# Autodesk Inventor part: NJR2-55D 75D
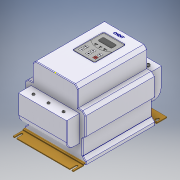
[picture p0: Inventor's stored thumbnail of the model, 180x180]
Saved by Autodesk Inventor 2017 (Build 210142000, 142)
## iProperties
Part Number: NJR2-55D 75D
Material: Типовые
Document SubType Name: Modeling
Designer: RSagdiev
Density: 1 g/cm^3
Appearance: По умолчанию
Author: RSagdiev
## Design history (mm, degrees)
sketch "Эскиз1"
  geometry: L1 (0, 0)-(14.471, 0) reference; L2 (0, 0)-(0, 21.118) reference; L3 (0, 0)-(230, 0); L4 (230, 0)-(230, 20); L5 (230, 215)-(0, 215); L6 (0, 215)-(0, 150); L7 (230, 20)-(0, 20); L8 (230, 70)-(0, 70); L9 (230, 70)-(230, 150); L10 (230, 20)-(230, 70); L11 (0, 70)-(0, 20); L12 (0, 20)-(0, 0); L13 (230, 150)-(0, 150); L14 (230, 150)-(230, 215); L15 (0, 150)-(0, 70)
  constraints: 30 end point, 17 parallel, 14 perpendicular, 3 horizontal, 2 vertical, 1 point on line
  dimensions: "d0" = 230 distance of L5.end L5.start; "d1" = 215 distance of L5.start L3.end; "d2" = 20 distance between parallel lines of L3 L7; "d3" = 50 distance between parallel lines of L8 L7; "d4" = 80 distance between parallel lines of L13 L8
extrude "Выдавливание1" new body sketch "Эскиз1" stored distance "d5" = 202; taper "d6" = 0 deg
extrude "Выдавливание2" join sketch "Эскиз1" stored distance "d7" = 180; taper "d8" = 0 deg
extrude "Выдавливание3" join sketch "Эскиз1" stored distance "d9" = 200; taper "d10" = 0 deg
extrude "Выдавливание4" join sketch "Эскиз1" stored distance "d11" = 150; taper "d12" = 0 deg
chamfer "Фаска1" distance "d13" = 10; stored, may be unused: second distance "d14" = 2, angle "d15" = 45 deg
sketch "Эскиз2"
  geometry: L1 (270, 0)-(236, 0); L2 (235, 1)-(235, 3); L3 (234, 4)-(-4, 4); L4 (-5, 3)-(-5, 1); L5 (-6, 0)-(-40, 0); L6 (230, 10)-(230, 0) reference; L7 (230, 0)-(0, 0) reference; L8 (0, 0)-(0, 10) reference; L9 (270, 3)-(238, 3); L10 (234, 7)-(-4, 7); L11 (-8, 3)-(-40, 3); L12 (-40, 0)-(-40, 3); L13 (270, 3)-(270, 0); A1 r 1 centre (-6, 1) between (-6, 0) and (-5, 1); A2 r 1 centre (-4, 3) between (-4, 4) and (-5, 3); A3 r 1 centre (236, 1) between (235, 1) and (236, 0); A4 r 1 centre (234, 3) between (235, 3) and (234, 4); A5 r 4 centre (234, 3) between (238, 3) and (234, 7); A6 r 4 centre (-4, 3) between (-4, 7) and (-8, 3); 4 further points
  constraints: 20 end point, 12 point on circle, 10 point on line, 8 tangent, 6 centre point, 4 perpendicular, 3 equal radius, 1 horizontal, 1 parallel, 4 other
  dimensions: "d16" = 4 distance of point (235, 0) point (235, 4); "d17" = 5 distance between parallel lines of L2 L6; "d18" = 4 distance between parallel lines of L7 L3; "d19" = 35 distance of point (235, 0) L1.start; "d20" = 35 distance of point (-5, 0) L5.end (= d19); "d21" = 4 distance of point (-5, 4) point (-5, 0) (derived); "d22" = 5 distance between parallel lines of L4 L8 (= d17); "d23" = 310 distance of L5.end L1.start (derived); "d24" = 1 radius of A1; "d25" = 3 distance between parallel lines of L1 L9
extrude "Выдавливание5" new body sketch "Эскиз2" stored distance "d26" = 200; taper "d27" = 0 deg
sketch "Эскиз4"
  geometry: L1 (272.5, 138)-(-42.5, 138); L2 (-42.5, 138)-(-42.5, 50); L3 (-42.5, 50)-(272.5, 50); L4 (272.5, 50)-(272.5, 138); L5 (230, 150)-(230, 205) reference; L6 (230, 150)-(0, 150) reference; L7 (230, 70)-(0, 70) reference; 1 further point
  constraints: 8 end point, 2 parallel, 1 horizontal, 1 perpendicular
  dimensions: "d28" = 315 distance between parallel lines of L2 L4; "d29" = 42.5 distance between parallel lines of L4 L5 (= -0.5 x d0 + 0.5 x d28); "d31" = 20 distance between parallel lines of L7 L3; "d34" = 12 distance between parallel lines of L1 L6
extrude "Выдавливание6" join sketch "Эскиз4" stored distance "d32" = 160; taper "d33" = 0 deg
fillet "Сопряжение1" dims "d35" = 25
sketch "Эскиз5" dims "d44" = 10
  geometry: L1 (160, 0)-(0, 0) reference; L2 (160, 42.5)-(160, 0) reference; L3 (160, 42.5)-(0, 42.5) reference; L4 (0, 0)-(0, 42.5) reference; C1 r 4 at (20, 20); C2 r 4 at (43.333, 20); C3 r 4 at (66.667, 20); C4 r 4 at (90, 20); C5 r 4 at (113.333, 20); C6 r 4 at (136.667, 20); 1 further point
  constraints: 6 centre point, 1 horizontal, 10 other
  dimensions: "d36" = 8 diameter of C1; "d37" = 160 distance between parallel lines of L2 L4 (derived); "d38" = 20 distance from line of C1.centre L4; "d41" = 23.33333 distance of C1.centre C2.centre (= -0.166667 x d38 + 0.166667 x d37)
  node "Спроецированная петля1"
extrude "Выдавливание7" cut sketch "Эскиз5" distance "d46" = 20; taper "d47" = 0 deg
extrude "Выдавливание8" new body sketch "Эскиз5" distance "d48" = 20; taper "d49" = 0 deg
sketch "Эскиз6" dims "d50" = 12, "d56" = 10
  geometry: L1 (0, 6)-(5.196, 3); L2 (5.196, 3)-(5.196, -3); L3 (5.196, -3)-(0, -6); L4 (0, -6)-(-5.196, -3); L5 (-5.196, -3)-(-5.196, 3); L6 (-5.196, 3)-(0, 6); L7 (140, 22.5)-(-20, 22.5) reference; L8 (23.333, 6)-(28.529, 3); L9 (28.529, 3)-(28.529, -3); L10 (28.529, -3)-(23.333, -6); L11 (23.333, -6)-(18.137, -3); L12 (18.137, -3)-(18.137, 3); L13 (18.137, 3)-(23.333, 6); L14 (46.667, 6)-(51.863, 3); L15 (51.863, 3)-(51.863, -3); L16 (51.863, -3)-(46.667, -6); L17 (46.667, -6)-(41.471, -3); L18 (41.471, -3)-(41.471, 3); L19 (41.471, 3)-(46.667, 6); L20 (70, 6)-(75.196, 3); L21 (75.196, 3)-(75.196, -3); L22 (75.196, -3)-(70, -6); L23 (70, -6)-(64.804, -3); L24 (64.804, -3)-(64.804, 3); L25 (64.804, 3)-(70, 6); L26 (93.333, 6)-(98.529, 3); L27 (98.529, 3)-(98.529, -3); L28 (98.529, -3)-(93.333, -6); L29 (93.333, -6)-(88.137, -3); L30 (88.137, -3)-(88.137, 3); L31 (88.137, 3)-(93.333, 6); L32 (116.667, 6)-(121.863, 3); L33 (121.863, 3)-(121.863, -3); L34 (121.863, -3)-(116.667, -6); L35 (116.667, -6)-(111.471, -3); L36 (111.471, -3)-(111.471, 3); L37 (111.471, 3)-(116.667, 6); 13 further points
  constraints: 72 end point, 6 coincident, 6 horizontal, 6 vertical alignment, 95 other
  dimensions: "d53" = 23.33333 distance of point (0, 0) point (23.333, 0) (= -0.166667 x d38 + 0.166667 x d37)
extrude "Выдавливание9" join sketch "Эскиз6" distance "d58" = 5; taper "d59" = 0 deg
sketch "Эскиз7"
  geometry: L1 (5.196, 3)-(0, 6) reference; L2 (0, 6)-(-5.196, 3) reference; L3 (-5.196, 3)-(-5.196, -3) reference; L4 (-5.196, -3)-(0, -6) reference; L5 (0, -6)-(5.196, -3) reference; L6 (5.196, -3)-(5.196, 3) reference; L7 (0, 3.691)-(3.196, 1.845); L8 (3.196, 1.845)-(3.196, -1.845); L9 (3.196, -1.845)-(0, -3.691); L10 (0, -3.691)-(-3.196, -1.845); L11 (-3.196, -1.845)-(-3.196, 1.845); L12 (-3.196, 1.845)-(0, 3.691); L13 (28.529, 3)-(23.333, 6) reference; L14 (23.333, 6)-(18.137, 3) reference; L15 (18.137, 3)-(18.137, -3) reference; L16 (18.137, -3)-(23.333, -6) reference; L17 (23.333, -6)-(28.529, -3) reference; L18 (28.529, -3)-(28.529, 3) reference; L19 (51.863, 3)-(46.667, 6) reference; L20 (46.667, 6)-(41.471, 3) reference; L21 (41.471, 3)-(41.471, -3) reference; L22 (41.471, -3)-(46.667, -6) reference; L23 (46.667, -6)-(51.863, -3) reference; L24 (51.863, -3)-(51.863, 3) reference; L25 (75.196, 3)-(70, 6) reference; L26 (70, 6)-(64.804, 3) reference; L27 (64.804, 3)-(64.804, -3) reference; L28 (64.804, -3)-(70, -6) reference; L29 (70, -6)-(75.196, -3) reference; L30 (75.196, -3)-(75.196, 3) reference; L31 (98.529, 3)-(93.333, 6) reference; L32 (93.333, 6)-(88.137, 3) reference; L33 (88.137, 3)-(88.137, -3) reference; L34 (88.137, -3)-(93.333, -6) reference; L35 (93.333, -6)-(98.529, -3) reference; L36 (98.529, -3)-(98.529, 3) reference; L37 (121.863, 3)-(116.667, 6) reference; L38 (116.667, 6)-(111.471, 3) reference; L39 (111.471, 3)-(111.471, -3) reference; L40 (111.471, -3)-(116.667, -6) reference; L41 (116.667, -6)-(121.863, -3) reference; L42 (121.863, -3)-(121.863, 3) reference; L43 (23.333, 3.691)-(26.529, 1.845); L44 (26.529, 1.845)-(26.529, -1.845); L45 (26.529, -1.845)-(23.333, -3.691); L46 (23.333, -3.691)-(20.137, -1.845); L47 (20.137, -1.845)-(20.137, 1.845); L48 (20.137, 1.845)-(23.333, 3.691); L49 (43.471, 1.845)-(46.667, 3.691); L50 (46.667, 3.691)-(49.863, 1.845); L51 (49.863, 1.845)-(49.863, -1.845); L52 (49.863, -1.845)-(46.667, -3.691); L53 (46.667, -3.691)-(43.471, -1.845); L54 (43.471, -1.845)-(43.471, 1.845); L55 (66.804, 1.845)-(70, 3.691); L56 (70, 3.691)-(73.196, 1.845); L57 (73.196, 1.845)-(73.196, -1.845); L58 (73.196, -1.845)-(70, -3.691); L59 (70, -3.691)-(66.804, -1.845); L60 (66.804, -1.845)-(66.804, 1.845); L61 (90.137, 1.845)-(93.333, 3.691); L62 (93.333, 3.691)-(96.529, 1.845); L63 (96.529, 1.845)-(96.529, -1.845); L64 (96.529, -1.845)-(93.333, -3.691)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; 1 further point
  constraints: 72 end point, 30 other
  dimensions: "d60" = 2 distance between parallel lines of L1 L7; "d61" = 2 distance between parallel lines of L13 L43; "d62" = 2 distance between parallel lines of L20 L49; "d63" = 2 distance between parallel lines of L26 L55; "d64" = 2 distance between parallel lines of L32 L61; "d65" = 2 distance between parallel lines of L38 L67
extrude "Выдавливание10" cut sketch "Эскиз7" distance "d66" = 1.5; taper "d67" = 0 deg
fillet "Сопряжение2" dims "d68" = 2
sketch "Эскиз8"
  geometry: L1 (0, -310)-(200, -310) reference; L2 (200, 0)-(0, 0) reference; L3 (200, 0)-(200, -34) reference; L4 (0, -34)-(0, 0) reference; L5 (8.5, -20)-(8.5, -25); L6 (191.5, -20)-(191.5, -25); L7 (8.5, -20)-(191.5, -20); L8 (8.5, -290)-(8.5, -310); L9 (5, -290)-(5, -310); L10 (12, -310)-(12, -290); L11 (8.5, -20)-(8.5, -290); L12 (8.5, -290)-(191.5, -290); L13 (191.5, -20)-(191.5, -290); L14 (191.5, -290)-(191.5, -310); L15 (188, -290)-(188, -310); L16 (195, -310)-(195, -290); A1 r 3.5 centre (8.5, -20) between (11.779, -21.225) and (5.221, -21.225); A2 r 5 centre (8.5, -25) between (5.221, -21.225) and (11.779, -21.225); A3 r 3.5 centre (191.5, -20) between (194.779, -21.225) and (188.221, -21.225); A4 r 5 centre (191.5, -25) between (188.221, -21.225) and (194.779, -21.225); A5 r 3.5 centre (8.5, -290) between (12, -290) and (5, -290); A6 r 3.5 centre (8.5, -310) between (5, -310) and (12, -310); A7 r 3.5 centre (191.5, -290) between (195, -290) and (188, -290); A8 r 3.5 centre (191.5, -310) between (188, -310) and (195, -310); 5 further points
  constraints: 28 end point, 16 point on circle, 8 centre point, 8 tangent, 4 vertical, 3 coincident, 2 horizontal, 2 midpoint, 2 parallel, 2 perpendicular, 2 point on line
  dimensions: "d69" = 183 distance of point (191.5, -20) point (8.5, -20); "d70" = 270 distance of L8.start point (8.5, -20); "d71" = 310 distance between parallel lines of L1 L2 (derived); "d72" = 20 distance from line of L2 point (8.5, -20) (= -0.5 x d70 + 0.5 x d71); "d73" = 200 distance between parallel lines of L3 L4 (derived); "d74" = 8.5 distance from line of L4 point (8.5, -20) (= -0.5 x d69 + 0.5 x d73); "d75" = 7 diameter of A1; "d76" = 10 diameter of A2; "d77" = 5 distance of L5.start L5.end; "d78" = 7 diameter of A3; "d79" = 10 diameter of A4; "d80" = 5 distance of L6.start L6.end; "d81" = 7 diameter of A6; "d82" = 7 diameter of A8
extrude "Выдавливание11" cut sketch "Эскиз8" distance "d83" = 5.5; taper "d84" = 0 deg
fillet "Сопряжение3" dims "d85" = 2
sketch "Эскиз9"
  geometry: L1 (130, 0)-(0, 0) reference; L2 (130, 226)-(130, 0) reference; L3 (0, 226)-(130, 226) reference; L4 (0, 0)-(0, 226) reference; L5 (33, 193)-(97, 193); L6 (100, 190)-(100, 96); L7 (97, 93)-(33, 93); L8 (30, 96)-(30, 190); L9 (97, 195)-(33, 195); L10 (28, 190)-(28, 96); L11 (33, 91)-(97, 91); L12 (102, 96)-(102, 190); A1 r 3 centre (33, 190) between (33, 193) and (30, 190); A2 r 3 centre (97, 190) between (100, 190) and (97, 193); A3 r 3 centre (97, 96) between (97, 93) and (100, 96); A4 r 3 centre (33, 96) between (30, 96) and (33, 93); A5 r 5 centre (33, 190) between (33, 195) and (28, 190); A6 r 5 centre (33, 96) between (28, 96) and (33, 91); A7 r 5 centre (97, 96) between (97, 91) and (102, 96); A8 r 5 centre (97, 190) between (102, 190) and (97, 195); 4 further points
  constraints: 16 end point, 16 point on circle, 8 centre point, 8 tangent, 6 point on line, 4 parallel, 3 equal radius, 2 perpendicular, 1 horizontal, 7 other
  dimensions: "d86" = 70 distance of point (100, 93) point (30, 93); "d87" = 100 distance of point (100, 193) point (100, 93); "d88" = 130 distance of L3.start L2.start (derived); "d89" = 226 distance of L1.end L3.start (derived); "d90" = 33 distance between parallel lines of L3 L5 (computed from d89, d87); "d91" = 30 distance between parallel lines of L4 L8 (= -0.5 x d86 + 0.5 x d88); "d92" = 3 radius of A1; "d93" = 2 distance between parallel lines of L5 L9
  node "Спроецированная петля8"
extrude "Выдавливание12" cut sketch "Эскиз9" distance "d94" = 25; taper "d95" = 0 deg
extrude "Выдавливание13" new body sketch "Эскиз9" distance "d96" = 25; taper "d97" = 0 deg
sketch "Эскиз10"
  geometry: L1 (30, 190)-(30, 150.574); L2 (33, 93)-(97, 93); L3 (100, 96)-(100, 150.574); L4 (97, 193)-(33, 193); L5 (97, 193)-(33, 193) reference; L6 (30, 190)-(30, 96) reference; L7 (30, 150.574)-(30, 96); L8 (100, 150.574)-(100, 190); L9 (45.628, 161.287)-(84.628, 161.287); L10 (87.628, 164.287)-(87.628, 176.287); L11 (84.628, 179.287)-(45.628, 179.287); L12 (42.628, 176.287)-(42.628, 164.287); L13 (42.628, 161.287)-(87.628, 179.287); L14 (87.628, 161.287)-(42.628, 179.287); A1 r 3 centre (33, 96) between (30, 96) and (33, 93); A2 r 3 centre (97, 96) between (97, 93) and (100, 96); A3 r 3 centre (97, 190) between (100, 190) and (97, 193); A4 r 3 centre (33, 190) between (33, 193) and (30, 190); A5 r 55 centre (65, 193) between (30, 150.574) and (100.197, 150.737); A6 r 3 centre (45.628, 176.287) between (45.628, 179.287) and (42.628, 176.287); A7 r 3 centre (45.628, 164.287) between (42.628, 164.287) and (45.628, 161.287); A8 r 3 centre (84.628, 176.287) between (87.628, 176.287) and (84.628, 179.287); A9 r 3 centre (84.628, 164.287) between (84.628, 161.287) and (87.628, 164.287); 2 further points
  constraints: 20 end point, 11 point on circle, 9 centre point, 9 point on line, 8 tangent, 3 equal radius, 3 midpoint, 2 parallel, 1 horizontal, 1 perpendicular
  dimensions: "d98" = 55 radius of A5; "d99" = 45 distance of L14.end L13.end; "d100" = 18 distance of L13.end L14.start; "d101" = 22.7132 distance from line of L4 point (65.128, 170.287); "d102" = 35.1281 distance from line of L1 point (65.128, 170.287); "d103" = 3 radius of A6 (derived)
extrude "Выдавливание14" cut sketch "Эскиз10" distance "d104" = 1; taper "d105" = 0 deg
sketch "Эскиз11"
  geometry: L1 (30, 150.574)-(30, 96) reference; L2 (33, 93)-(97, 93) reference; L3 (100, 96)-(100, 150.574) reference; L4 (30, 150.574)-(30, 96) reference; L5 (30, 123)-(100, 123); L6 (100, 96)-(100, 150.574) reference; L7 (30, 108)-(100, 108); L8 (33, 93)-(97, 93) reference; L9 (41.667, 93)-(41.667, 143.195); L10 (88.333, 93)-(88.333, 143.195); L11 (65, 93)-(65, 138); L12 (36.667, 128)-(46.667, 128); L13 (46.667, 128)-(46.667, 118); L14 (46.667, 118)-(36.667, 118); L15 (36.667, 118)-(36.667, 128); L16 (36.667, 128)-(46.667, 118); L17 (46.667, 128)-(36.667, 118); L18 (36.667, 113)-(46.667, 113); L19 (46.667, 113)-(46.667, 103); L20 (46.667, 103)-(36.667, 103); L21 (36.667, 103)-(36.667, 113); L22 (36.667, 113)-(46.667, 103); L23 (46.667, 113)-(36.667, 103); L24 (60, 128)-(70, 128); L25 (70, 128)-(70, 118); L26 (70, 118)-(60, 118); L27 (60, 118)-(60, 128); L28 (60, 128)-(70, 118); L29 (70, 128)-(60, 118); L30 (60, 113)-(70, 113); L31 (70, 113)-(70, 103); L32 (70, 103)-(60, 103); L33 (60, 103)-(60, 113); L34 (60, 113)-(70, 103); L35 (70, 113)-(60, 103); L36 (83.333, 128)-(93.333, 128); L37 (93.333, 128)-(93.333, 118); L38 (93.333, 118)-(83.333, 118); L39 (83.333, 118)-(83.333, 128); L40 (83.333, 128)-(93.333, 118); L41 (93.333, 128)-(83.333, 118); L42 (83.333, 113)-(93.333, 113); L43 (93.333, 113)-(93.333, 103); L44 (93.333, 103)-(83.333, 103); L45 (83.333, 103)-(83.333, 113); L46 (83.333, 113)-(93.333, 103); L47 (93.333, 113)-(83.333, 103); L48 (46.767, 128.1)-(36.567, 128.1); L49 (36.567, 128.1)-(36.567, 117.9); L50 (36.567, 117.9)-(46.767, 117.9); L51 (46.767, 117.9)-(46.767, 128.1); L52 (70.1, 128.1)-(59.9, 128.1); L53 (59.9, 128.1)-(59.9, 117.9); L54 (59.9, 117.9)-(70.1, 117.9); L55 (70.1, 117.9)-(70.1, 128.1); L56 (93.433, 128.1)-(83.233, 128.1); L57 (83.233, 128.1)-(83.233, 117.9); L58 (83.233, 117.9)-(93.433, 117.9); L59 (93.433, 117.9)-(93.433, 128.1); L60 (46.767, 113.1)-(36.567, 113.1); L61 (36.567, 113.1)-(36.567, 102.9); L62 (36.567, 102.9)-(46.767, 102.9); L63 (46.767, 102.9)-(46.767, 113.1); L64 (70.1, 113.1)-(59.9, 113.1)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; A1 r 55 centre (65, 193) between (30, 150.574) and (100, 150.574) reference; A2 r 3 centre (33, 96) between (30, 96) and (33, 93) reference; A3 r 3 centre (97, 96) between (97, 93) and (100, 96) reference; A4 r 55 centre (65, 193) between (30, 150.574) and (100, 150.574) reference; 8 further points
  constraints: 130 end point, 24 parallel, 16 midpoint, 16 point on line, 14 perpendicular, 7 horizontal, 4 point on circle, 1 vertical, 18 other
  dimensions: "d106" = 70 distance between parallel lines of L3 L1 (derived); "d107" = 45 distance from line of L2 L11.end (derived); "d108" = 15 distance between parallel lines of L7 L5 (= 0.333333 x d107); "d109" = 15 distance from line of L11.end L5 (= 0.333333 x d107); "d110" = 23.33333 distance between parallel lines of L11 L10 (= 0.333333 x d106); "d111" = 23.33333 distance between parallel lines of L11 L9 (= d110); "d112" = 10 distance of L13.end L14.end; "d113" = 10 distance of L12.end L13.end; "d114" = 10 distance of L19.end L20.end; "d115" = 10 distance of L18.end L19.end; "d116" = 10 distance of L25.end L26.end; "d117" = 10 distance of L24.end L25.end; "d118" = 10 distance of L31.end L32.end; "d119" = 10 distance of L30.end L31.end; "d120" = 10 distance of L37.end L38.end; "d121" = 10 distance of L36.end L37.end; "d122" = 10 distance of L43.end L44.end; "d123" = 10 distance of L42.end L43.end; "d124" = 0.1 distance between parallel lines of L12 L48; "d125" = 0.1 distance between parallel lines of L24 L52; "d126" = 0.1 distance between parallel lines of L36 L56; "d127" = 0.1 distance between parallel lines of L18 L60; "d128" = 0.1 distance between parallel lines of L30 L64; "d129" = 0.1 distance between parallel lines of L42 L68
extrude "Выдавливание15" cut sketch "Эскиз11" distance "d130" = 3; taper "d131" = 0 deg
sketch "Эскиз12"
  geometry: L1 (100, 96)-(100, 150.574) reference; L2 (50, 144.701)-(80, 144.701); C1 r 1.5 at (65, 144.701); C2 r 1.5 at (80, 144.701); C3 r 1.5 at (50, 144.701); C4 r 1.6 at (50, 144.701); C5 r 1.6 at (65, 144.701); C6 r 1.6 at (80, 144.701); A1 r 55 centre (65, 193) between (30, 150.574) and (100, 150.574) reference; 1 further point
  constraints: 6 centre point, 2 end point, 1 coincident, 1 horizontal, 1 midpoint
  dimensions: "d132" = 3 diameter of C1; "d133" = 3 diameter of C2; "d134" = 3 diameter of C3; "d135" = 48.29941 distance of A1.centre C1.centre; "d136" = 35 distance from line of L1 C1.centre; "d137" = 15 distance of C1.centre C2.centre; "d138" = 15 distance of C1.centre L2.start; "d139" = 0.1 radial gap between concentric circles of C3 C4; "d140" = 0.1 radial gap between concentric circles of C1 C5; "d141" = 0.1 radial gap between concentric circles of C2 C6
extrude "Выдавливание16" cut sketch "Эскиз12" distance "d142" = 3; taper "d143" = 0 deg
sketch "Эскиз13"
  geometry: L1 (45, 150.348)-(102.075, 150.348); L2 (102.075, 150.348)-(102.075, 146.701); L3 (102.075, 146.701)-(45, 146.701); L4 (45, 146.701)-(45, 150.348); C1 r 1.5 at (50, 144.701) reference; 1 further point
  constraints: 2 other
  dimensions: "d144" = 2 vertical distance of L3.end C1.centre; "d145" = 5 horizontal distance of C1.centre L3.end
feature "Рельеф1" sketch "Эскиз13" dims "d146" = 0.1, "d147" = 0
sketch "Эскиз14"
  geometry: L1 (36.734, 124.406)-(51.145, 124.406); L2 (51.145, 124.406)-(51.145, 120.906); L3 (51.145, 120.906)-(36.734, 120.906); L4 (36.734, 120.906)-(36.734, 124.406); L5 (38.873, 106.059)-(38.873, 109.559); L6 (38.873, 109.559)-(53.285, 109.559); L7 (53.285, 109.559)-(53.285, 106.059); L8 (53.285, 106.059)-(38.873, 106.059); L9 (84.699, 105.985)-(84.699, 109.485); L10 (84.699, 109.485)-(99.11, 109.485); L11 (99.11, 109.485)-(99.11, 105.985); L12 (99.11, 105.985)-(84.699, 105.985); L13 (85.21, 120.906)-(85.21, 124.406); L14 (85.21, 124.406)-(99.621, 124.406); L15 (99.621, 124.406)-(99.621, 120.906); L16 (99.621, 120.906)-(85.21, 120.906); 1 further point
  constraints: 8 other
feature "Рельеф2" dims "d148" = 0.1, "d149" = 0
feature "Рельеф3" dims "d150" = 0.1, "d151" = 0
feature "Рельеф4" dims "d152" = 0.1, "d153" = 0
feature "Рельеф5" dims "d154" = 0.1, "d155" = 0
sketch "Эскиз15" dims "d156" = 6, "d157" = 6
  geometry: L1 (60, 128)-(60, 118) reference; L2 (60, 118)-(70, 118) reference; L3 (70, 118)-(70, 128) reference; L4 (70, 128)-(60, 128) reference; L5 (60, 113)-(60, 103) reference; L6 (60, 103)-(70, 103) reference; L7 (70, 103)-(70, 113) reference; L8 (70, 113)-(60, 113) reference; L9 (60, 118)-(70, 128); L10 (60, 128)-(70, 118); L11 (60, 113)-(70, 103); L12 (70.1, 113.1)-(70.1, 102.9) reference; L13 (70.1, 113.1)-(60, 103); L14 (65.05, 126)-(67.573, 121.457); L15 (67.573, 121.457)-(62.377, 121.544); L16 (62.377, 121.544)-(65.05, 126); L17 (65.05, 105.05)-(62.452, 109.55); L18 (62.452, 109.55)-(67.648, 109.55); L19 (67.648, 109.55)-(65.05, 105.05); 5 further points
  constraints: 20 end point, 2 coincident, 2 midpoint, 2 perpendicular, 1 parallel, 1 vertical alignment, 19 other
  node "Спроецированная петля11"
  node "Спроецированная петля12"
feature "Рельеф6" dims "d158" = 0.1, "d159" = 0
feature "Рельеф7" dims "d160" = 0.1, "d161" = 0
sketch "Эскиз16"
  geometry: L1 (2, -42.5)-(158, -42.5) reference; L2 (160, 0)-(160, -40.5) reference; L3 (0, 0)-(160, 0) reference; L4 (0, -40.5)-(0, 0) reference; L5 (130, -22.5)-(0, -22.5); L6 (0, -40.5)-(0, -17.5) reference; C1 r 4 at (30, -22.5); C2 r 4 at (80, -22.5); C3 r 4 at (130, -22.5); A1 r 2 centre (2, -40.5) between (0, -40.5) and (2, -42.5) reference; A2 r 2 centre (158, -40.5) between (158, -42.5) and (160, -40.5) reference; 1 further point
  constraints: 3 centre point, 3 point on line, 2 end point, 1 horizontal
  dimensions: "d162" = 8 diameter of C1; "d163" = 8 diameter of C2; "d164" = 8 diameter of C3; "d165" = 30 distance from line of L2 L5.start; "d166" = 20 distance from line of L5.start L1; "d167" = 50 distance of C2.centre L5.start; "d168" = 50 distance of C1.centre C2.centre
extrude "Выдавливание17" new body sketch "Эскиз16" distance "d169" = 3; taper "d170" = 0 deg
sketch "Эскиз17"
  geometry: L1 (-28, -20)-(128, -20) reference; L2 (130, 22.5)-(130, -18) reference; L3 (-30, 22.5)-(130, 22.5) reference; L4 (-30, -18)-(-30, 22.5) reference; L5 (0, 3)-(2.598, 1.5); L6 (2.598, 1.5)-(2.598, -1.5); L7 (2.598, -1.5)-(0, -3); L8 (0, -3)-(-2.598, -1.5); L9 (-2.598, -1.5)-(-2.598, 1.5); L10 (-2.598, 1.5)-(0, 3); L11 (50, 3)-(52.598, 1.5); L12 (52.598, 1.5)-(52.598, -1.5); L13 (52.598, -1.5)-(50, -3); L14 (50, -3)-(47.402, -1.5); L15 (47.402, -1.5)-(47.402, 1.5); L16 (47.402, 1.5)-(50, 3); L17 (100, 3)-(102.598, 1.5); L18 (102.598, 1.5)-(102.598, -1.5); L19 (102.598, -1.5)-(100, -3); L20 (100, -3)-(97.402, -1.5); L21 (97.402, -1.5)-(97.402, 1.5); L22 (97.402, 1.5)-(100, 3); C1 r 4 at (0, 0) reference; C2 r 4 at (50, 0) reference; C3 r 4 at (100, 0) reference; C4 r 4 at (50, 0) reference; A1 r 2 centre (-28, -18) between (-30, -18) and (-28, -20) reference; A2 r 2 centre (128, -18) between (128, -20) and (130, -18) reference; 4 further points
  constraints: 36 end point, 3 coincident, 3 vertical alignment, 45 other
  dimensions: "d171" = 1 dimension on C1; "d172" = 1 dimension on C2; "d173" = 1 dimension on C3
extrude "Выдавливание18" cut sketch "Эскиз17" distance "d174" = 0.5; taper "d175" = 0 deg
fillet "Сопряжение4" dims "d176" = 1
sketch "Эскиз18"
  geometry: L1 (46.683, 214.728)-(62.561, 214.728); L2 (62.561, 214.728)-(62.561, 211.091); L3 (62.561, 211.091)-(46.683, 211.091); L4 (46.683, 211.091)-(46.683, 214.728); 1 further point
  constraints: 2 other
feature "Рельеф8" sketch "Эскиз18" dims "d177" = 0.1, "d178" = 0
node "Твердое тело1"
node "Твердое тело2"
node "Твердое тело3"
node "Спроецированная петля2"
node "Спроецированная петля3"
node "Спроецированная петля4"
node "Спроецированная петля5"
node "Спроецированная петля6"
node "Спроецированная петля7"
node "Твердое тело4"
node "Спроецированная петля10"
node "Спроецированная петля13"
node "Твердое тело5"
node "Спроецированная петля14"
node "Спроецированная петля15"
node "Спроецированная петля16"
node "Спроецированная петля17"
